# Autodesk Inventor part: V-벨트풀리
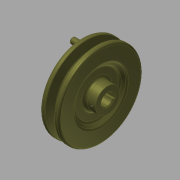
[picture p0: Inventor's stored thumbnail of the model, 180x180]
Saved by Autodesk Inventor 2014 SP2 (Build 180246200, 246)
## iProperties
Company: 한국ATC센터
Created: 2015-12
Part Number: V-벨트풀리
Document SubType Name: Modeling
Designer: mdu
Density: 7.25 g/cm^3
Mass: 596.622 g
Surface Area: 212.232 cm^2
Volume: 82.2927 cm^3
Material: 주철
Appearance: 티타늄
Author: mdu
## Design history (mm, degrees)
sketch "스케치1"
  geometry: L1 (-13, 0)-(13, 0); L2 (-13, 0)-(-13, 12.5); L3 (-13, 12.5)-(-9, 12.5); L4 (-9, 12.5)-(-9, 23); L5 (-9, 23)-(-13, 27); L6 (-13, 27)-(-13, 42.7); L7 (-13, 42.7)-(-8.325, 42.7); L8 (-8.325, 42.7)-(-5.574, 33.7); L9 (-5.574, 33.7)-(-1.426, 33.7); L10 (-1.426, 33.7)-(1.325, 42.7); L11 (1.325, 42.7)-(6, 42.7); L12 (6, 42.7)-(6, 27); L13 (6, 27)-(2, 23); L14 (2, 23)-(2, 12.5); L15 (2, 12.5)-(13, 12.5); L16 (13, 12.5)-(13, 0); L17 (-7.5, 40)-(0.5, 40); 2 further points
  constraints: 34 end point, 6 parallel, 5 collinear, 5 equal length, 4 perpendicular, 2 point on line, 1 coincident, 1 horizontal, 1 midpoint
  dimensions: "d0" = 26 distance of L1.start L1.end; "d1" = 2.7 distance between parallel lines of L7 L17; "d2" = 6.3 distance between parallel lines of L9 L17; "d3" = 8 distance of L17.start L17.end; "d4" = 34 deg angle of L10 L8; "d5" = 19 distance between parallel lines of L12 L6; "d7" = 25 diameter of L15 L1; "d8" = 46 diameter of L13.end L1; "d9" = 54 diameter of L12.end L1; "d10" = 4 distance between parallel lines of L2 L4; "d11" = 80 diameter of L17 L1
revolve "회전1" sketch "스케치1" stored, may be unused: angle "d12" = 90 deg
sketch "스케치2"
  geometry: L1 (-2, 5.657)-(-2, 7.8); L2 (-2, 7.8)-(2, 7.8); L3 (2, 7.8)-(2, 5.657); A1 r 6 centre (0, 0) between (-2, 5.657) and (2, 5.657); 1 further point
  constraints: 6 end point, 2 parallel, 2 point on circle, 1 centre point, 1 coincident, 1 perpendicular, 1 vertical
  dimensions: "d13" = 12 diameter of A1; "d14" = 13.8 dimension on A1 L2; "d15" = 4 distance of L1.end L2.end
extrude "돌출1" cut sketch "스케치2" stored distance "d16" = 10; taper "d17" = 0 deg
node "작업 평면1"
sketch "스케치3"
  geometry: L1 (-5.5, 12.5)-(-5.5, -12.5) reference; L2 (20.5, 27)-(20.5, -27) reference; 3 further points
  constraints: 1 horizontal alignment, 1 midpoint
  dimensions: "d18" = 4 distance from line of point (-1.5, 0) L1; "d33" = 22 distance from line of point (-1.5, 0) L2 (derived)
hole "구멍1" sketch "스케치3" at (-1.5, 0) diameter "d19" = 2.459; stored, may be unused: countersink angle "d23" = 90 deg, drill point angle "d25" = 118 deg; dims "d20" = 6, "d21" = 4, "d22" = 2, "d24" = 8
fillet "모깎기1" dims "d26" = 2, "d27" = 0.5, "d28" = 1, "d29" = 3
chamfer "모따기1" distance "d30" = 1; stored, may be unused: second distance "d31" = 2, angle "d32" = 45 deg
sketch "스케치4" dims "d35" = 70
  geometry: C1 r 3 at (35, 0); 2 further points
  constraints: 2 horizontal alignment, 1 centre point, 1 coincident, 2 other
  dimensions: "d34" = 6 diameter of C1
extrude "돌출2" join sketch "스케치4" distance "d36" = 10; taper "d37" = 0 deg
fillet "모깎기2" dims "d38" = 0.5, "d39" = 1
node "솔리드1"
